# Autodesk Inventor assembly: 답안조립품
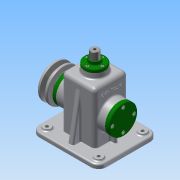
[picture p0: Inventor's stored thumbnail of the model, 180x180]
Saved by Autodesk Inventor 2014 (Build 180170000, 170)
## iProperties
Created: 2015-12
Part Number: 답안조립품
Document SubType Name: Assembly
Designer: Administrator
Author: Administrator
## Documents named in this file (18)
- D:\451225V1006\답안조립품.iam
- D:\451225V1006\1-본체.ipt
- D:\451225V1006\베어링 15 x 35 x 11.ipt
- D:\451225V1006\뒤커버.ipt
- D:\451225V1006\편심축.ipt
- D:\451225V1006\멈춤링 15 x 1.ipt
- D:\451225V1006\링크.ipt
- D:\451225V1006\고정핀.ipt
- D:\451225V1006\슬라이드바.ipt
- D:\451225V1006\멈춤링 6 x 5.ipt
- D:\451225V1006\상부부시.ipt
- D:\451225V1006\볼트 M3 x 8.ipt
- D:\451225V1006\앞커버.ipt
- D:\451225V1006\볼트 M4 x 10.ipt
- D:\451225V1006\키 5 x 5 x 14.ipt
- D:\451225V1006\와셔.ipt
- D:\451225V1006\볼트 M6 x 12.ipt
- D:\451225V1006\V-벨트풀리.ipt
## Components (16 placed, 6 different names)
1. 1-본체:1
2. 고정핀:1 — 플러쉬:2
3. ISO 4018 M6 x 12:1
4. V-벨트풀리:1 — 플러쉬:3, 각도:2
5. ISO 4762 M3 x 8:1
6. ISO 4762 M3 x 8:2
7. ISO 4762 M3 x 8:3
8. ISO 4762 M3 x 8:4
9. ISO 4762 M4 x 10:1
10. ISO 4762 M4 x 10:3
11. ISO 4762 M4 x 10:4
12. ISO 4762 M4 x 10:5
13. ISO 4762 M4 x 10:2
14. ISO 4762 M4 x 10:6
15. ISO 4762 M4 x 10:7
16. ISO 4762 M4 x 10:8
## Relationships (3: Flush 2, Angle 1)
- 플러쉬:2 [Flush]: 고정핀:1
- 플러쉬:3 [Flush]: V-벨트풀리:1
- 각도:2 [Angle]: V-벨트풀리:1
